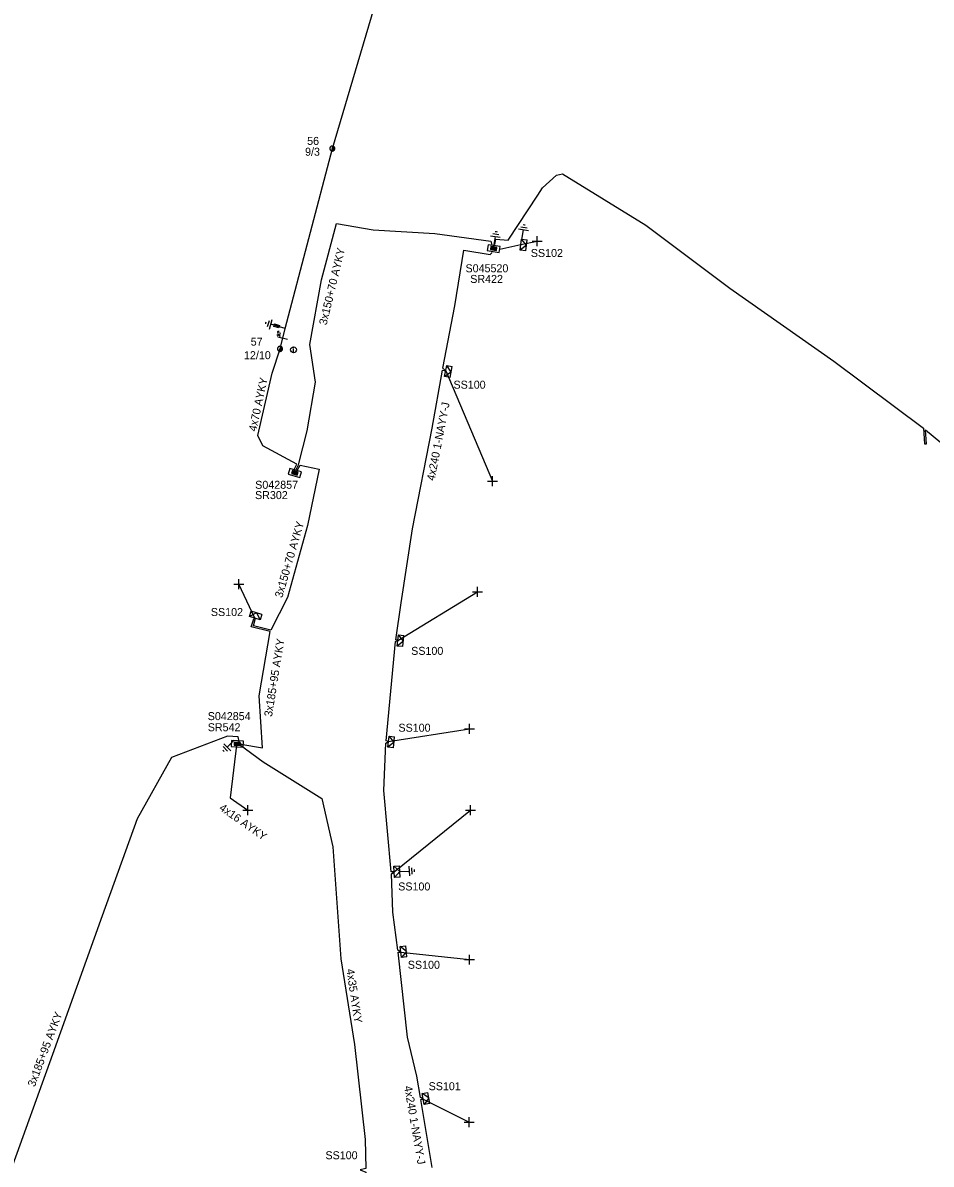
# Model space of a CAD drawing. Extents: x -748492 to -735633, y -1146251 to -1139940.
# Drawn here: x -736574.3 to -736460.8, y -1143691.4 to -1143548.7 of the extents above; entities that cross this region are included whole.
import ezdxf

# ---------------------------------------------------------------- set-up
doc = ezdxf.new("R2010")
doc.units = 0
for name, color, linetype in [('Vrstva 1', 7, 'Continuous'), ('Vrstva 10', 7, 'Continuous'), ('Vrstva 12', 7, 'Continuous'), ('Vrstva 13', 7, 'Continuous'), ('Vrstva 14', 7, 'Continuous'), ('Vrstva 15', 7, 'Continuous'), ('Vrstva 16', 7, 'Continuous'), ('Vrstva 18', 7, 'Continuous'), ('Vrstva 2', 7, 'Continuous'), ('Vrstva 28', 7, 'Continuous'), ('Vrstva 29', 7, 'Continuous'), ('Vrstva 30', 7, 'Continuous'), ('Vrstva 31', 7, 'Continuous'), ('Vrstva 33', 7, 'Continuous'), ('Vrstva 34', 7, 'Continuous'), ('Vrstva 36', 7, 'Continuous'), ('Vrstva 5', 7, 'Continuous'), ('Vrstva 52', 7, 'Continuous'), ('Vrstva 54', 7, 'Continuous'), ('Vrstva 59', 7, 'Continuous'), ('Vrstva 6', 7, 'Continuous'), ('Vrstva 8', 7, 'Continuous'), ('Vrstva 9', 7, 'Continuous')]:
    doc.layers.add(name, color=color, linetype=linetype)

# ---------------------------------------------------------------- blocks, each defined once
blk = doc.blocks.new('NN440')
at = {"layer": 'Vrstva 2'}
for points in [[(0.63, 0), (0.63, 0.06), (0.62, 0.13), (0.6, 0.19), (0.58, 0.25), (0.55, 0.31), (0.51, 0.37), (0.47, 0.42), (0.42, 0.46), (0.37, 0.51), (0.32, 0.54), (0.26, 0.57), (0.2, 0.59), (0.13, 0.61), (0.07, 0.62), (0, 0.63), (-0.06, 0.62), (-0.13, 0.61), (-0.19, 0.59), (-0.26, 0.57), (-0.31, 0.54), (-0.37, 0.51), (-0.42, 0.46), (-0.47, 0.42), (-0.51, 0.37), (-0.54, 0.31), (-0.57, 0.25), (-0.6, 0.19), (-0.62, 0.13), (-0.63, 0.06), (-0.63, 0), (-0.63, -0.07), (-0.62, -0.14), (-0.6, -0.2), (-0.57, -0.26), (-0.54, -0.32), (-0.51, -0.37), (-0.47, -0.43), (-0.42, -0.47), (-0.37, -0.51), (-0.31, -0.55), (-0.26, -0.58), (-0.19, -0.6), (-0.13, -0.62), (-0.06, -0.63), (0, -0.63), (0.07, -0.63), (0.13, -0.62), (0.2, -0.6), (0.26, -0.58), (0.32, -0.55), (0.37, -0.51), (0.42, -0.47), (0.47, -0.43), (0.51, -0.37), (0.55, -0.32), (0.58, -0.26), (0.6, -0.2), (0.62, -0.14), (0.63, -0.07), (0.63, 0)], [(-0.63, 0), (0.63, 0)], [(-0.6, -0.18), (0.57, -0.18)], [(-0.51, -0.32), (0.5, -0.32)], [(-0.37, -0.47), (0.35, -0.47)]]:
    blk.add_lwpolyline(points, dxfattribs=at)
blk = doc.blocks.new('NN840')
at = {"layer": 'Vrstva 15'}
for points in [[(0, 0.62), (0, -0.63)], [(-0.75, -0.71), (-0.75, -0.66)], [(-0.73, -0.76), (-0.75, -0.71)], [(-0.66, -0.8), (-0.73, -0.76)], [(-0.63, -0.8), (-0.66, -0.8)], [(-0.56, -0.76), (-0.63, -0.8)], [(-0.54, -0.71), (-0.56, -0.76)], [(-0.54, -0.38), (-0.54, -0.71)], [(-0.33, -0.38), (-0.33, -0.8)], [(-0.33, -0.64), (-0.13, -0.38)], [(-0.26, -0.56), (-0.09, -0.8)]]:
    blk.add_lwpolyline(points, dxfattribs=at)
blk = doc.blocks.new('NN770')
at = {"layer": 'Vrstva 10'}
for p, q in [((0, 0.19), (0, 0.26)), ((0, -0.28), (0, 0.11))]:
    blk.add_line(p, q, dxfattribs=at)
blk.add_circle((0, -0.01), 0.375, dxfattribs=at)
blk = doc.blocks.new('NN800')
at = {"layer": 'Vrstva 1'}
for points in [[(-0.44, 0.44), (0.44, -0.44)], [(-0.44, -0.44), (0.44, 0.44)]]:
    blk.add_lwpolyline(points, dxfattribs=at)
blk = doc.blocks.new('NN820')
at = {"layer": 'Vrstva 13'}
for points in [[(0, 0), (0, -1.05)], [(-0.16, -0.81), (0.16, -0.81)], [(-0.16, -1.47), (-0.16, -0.81)], [(0, -1.05), (-0.06, -0.93)], [(0, -1.05), (0.06, -0.93)], [(0.16, -0.81), (0.16, -1.47)], [(0.16, -1.47), (-0.16, -1.47)], [(0, -1.47), (0, -1.87)]]:
    blk.add_lwpolyline(points, dxfattribs=at)
blk = doc.blocks.new('NN620')
at = {"layer": 'Vrstva 8'}
for points in [[(0.75, 0), (-0.75, 0)], [(-0.75, 0), (-0.75, -0.75)], [(0.75, -0.75), (0.75, 0)], [(-0.75, -0.75), (0.75, -0.75)], [(0.37, -0.18), (-0.38, -0.18)], [(-0.38, -0.18), (-0.38, -0.56)], [(-0.38, -0.56), (0.37, -0.56)], [(0.32, -0.23), (-0.33, -0.23)], [(-0.33, -0.23), (-0.33, -0.51)], [(-0.33, -0.51), (0.32, -0.51)], [(0.27, -0.27), (-0.28, -0.27)], [(-0.28, -0.27), (-0.28, -0.46)], [(-0.28, -0.46), (0.27, -0.46)], [(0.23, -0.32), (-0.23, -0.32)], [(-0.23, -0.32), (-0.23, -0.42)], [(-0.23, -0.42), (0.23, -0.42)], [(-0.19, -0.37), (0.19, -0.37)], [(0.23, -0.42), (0.23, -0.32)], [(0.27, -0.46), (0.27, -0.27)], [(0.32, -0.51), (0.32, -0.23)], [(0.37, -0.56), (0.37, -0.18)]]:
    blk.add_lwpolyline(points, dxfattribs=at)
blk = doc.blocks.new('NN630')
at = {"layer": 'Vrstva 9'}
for points in [[(0, -0.7), (-0.7, 0)], [(-0.7, -0.7), (-0.7, 0), (0.7, 0), (0.7, -0.7)], [(-0.7, -0.7), (0.7, -0.7)], [(0, -0.7), (0.7, 0)]]:
    blk.add_lwpolyline(points, dxfattribs=at)
blk = doc.blocks.new('NN810')
at = {"layer": 'Vrstva 14'}
for points in [[(0, -0.64), (0, -1.89)], [(0.63, -1.89), (-0.62, -1.89)], [(0.39, -2.2), (-0.4, -2.2)], [(0, -2.52), (-0.12, -2.52)], [(0.14, -2.52), (0, -2.52)]]:
    blk.add_lwpolyline(points, dxfattribs=at)

msp = doc.modelspace()

# ---------------------------------------------------------------- linework, layer by layer
at = {"layer": 'Vrstva 1'}
msp.add_lwpolyline([(-736542.15, -1143589.49), (-736541.49, -1143586.96), (-736535.61, -1143564.45), (-736528.19, -1143539.37), (-736522.07, -1143513.24)], dxfattribs=at)
at = {"layer": 'Vrstva 5'}
for points in [[(-736515.32, -1143576.46), (-736515.17, -1143575.77), (-736513.66, -1143575.89), (-736509.94, -1143570.26), (-736509.33, -1143569.38), (-736507.61, -1143567.78), (-736506.87, -1143567.6), (-736496.45, -1143574.03), (-736485.93, -1143581.91), (-736472.94, -1143591.01), (-736461.73, -1143599.42), (-736461.61, -1143601.38), (-736461.36, -1143601.36), (-736461.47, -1143599.62), (-736453.1, -1143606.51), (-736442.54, -1143614.26), (-736434.94, -1143619.81), (-736423.45, -1143627.86), (-736416.15, -1143633.12), (-736416.73, -1143634), (-736417.1, -1143633.9)], [(-736540.19, -1143604.64), (-736539.85, -1143603.98), (-736538.75, -1143599.72), (-736537.71, -1143593.65), (-736538.41, -1143588.96), (-736536.96, -1143580.85), (-736535.08, -1143573.83), (-736530.5, -1143574.62), (-736522.8, -1143575.07), (-736515.82, -1143576.03), (-736515.7, -1143576.52)], [(-736514.69, -1143577.04), (-736512.06, -1143576.46)], [(-736523.15, -1143691.81), (-736524.57, -1143683.32), (-736524.25, -1143683.26), (-736524.61, -1143683.08), (-736525.07, -1143680.42), (-736526.2, -1143675.54), (-736527.37, -1143664.91), (-736527.06, -1143664.89), (-736527.41, -1143664.64), (-736528.05, -1143659.91), (-736528.23, -1143655.11), (-736527.89, -1143654.87), (-736528.24, -1143654.88), (-736529.17, -1143644.71), (-736528.91, -1143638.78), (-736528.6, -1143638.59), (-736528.9, -1143638.5), (-736527.7, -1143626.09), (-736527.43, -1143625.94), (-736527.68, -1143625.85), (-736527.01, -1143621.25), (-736525.59, -1143611.98), (-736523.13, -1143599.41), (-736521.86, -1143592.16), (-736521.45, -1143592.25), (-736521.81, -1143591.9), (-736520.29, -1143584.12), (-736519.18, -1143577.15), (-736515.87, -1143577.69), (-736515.62, -1143577.43)], [(-736540.39, -1143604.58), (-736540.03, -1143603.89), (-736544.29, -1143601.63), (-736544.93, -1143600.33), (-736543.15, -1143592.53), (-736542.15, -1143589.49)], [(-736539.99, -1143604.7), (-736539.65, -1143604.02), (-736537.24, -1143604.52), (-736538.7, -1143611.59), (-736541.23, -1143620.59), (-736543.3, -1143624.64), (-736545.48, -1143624.11), (-736545.25, -1143623.32), (-736545.3, -1143623.15)], [(-736547.11, -1143638.69), (-736547.06, -1143638.89), (-736544.35, -1143639.36), (-736544.76, -1143632.86), (-736543.37, -1143624.83), (-736545.74, -1143624.25), (-736545.44, -1143623.25), (-736545.3, -1143623.15)], [(-736547.25, -1143638.56), (-736547.4, -1143637.97), (-736548.7, -1143637.89), (-736555.69, -1143640.57), (-736559.98, -1143648.22), (-736564.36, -1143660.36), (-736570.59, -1143677.69), (-736575.95, -1143692.63), (-736580.47, -1143701.63), (-736583.04, -1143702.99), (-736590.32, -1143701.54), (-736594.79, -1143700.58), (-736606.16, -1143696.36), (-736617.69, -1143691.44), (-736617.29, -1143689.85)], [(-736547.32, -1143638.69), (-736547.27, -1143638.89), (-736544.27, -1143641.1), (-736536.92, -1143645.7), (-736535.56, -1143651.72), (-736534.56, -1143665.73), (-736532.86, -1143676.43), (-736531.53, -1143688.34), (-736531.41, -1143691.93), (-736532.12, -1143692.13), (-736531.43, -1143692.42), (-736530.87, -1143708.45), (-736532.82, -1143708.54)]]:
    msp.add_lwpolyline(points, dxfattribs=at)
at = {"layer": 'Vrstva 52'}
msp.add_lwpolyline([(-736547.55, -1143638.68), (-736548.39, -1143645.61), (-736546.17, -1143647.17)], dxfattribs=at)
at = {"layer": 'Vrstva 59'}
for points in [[(-736512.06, -1143576.46), (-736510.03, -1143576.02)], [(-736521.45, -1143592.25), (-736515.59, -1143606.02)], [(-736545.3, -1143623.15), (-736547.3, -1143618.9)], [(-736527.43, -1143625.94), (-736517.46, -1143619.86)], [(-736528.6, -1143638.59), (-736518.46, -1143637)], [(-736527.89, -1143654.87), (-736518.35, -1143647.16)], [(-736527.06, -1143664.89), (-736518.47, -1143665.83)], [(-736524.25, -1143683.26), (-736518.53, -1143686.16)]]:
    msp.add_lwpolyline(points, dxfattribs=at)

# ---------------------------------------------------------------- block references
at = {"layer": 'Vrstva 13', "xscale": 0.5}
for p, yscale, rotation in [((-736535.61, -1143564.45), 0.5, 75.52877971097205), ((-736542.15, -1143589.49), 0.49999999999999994, 73.19172953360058)]:
    msp.add_blockref('NN440', p, dxfattribs=dict(at, yscale=yscale, rotation=rotation))
at = {"layer": 'Vrstva 15'}
for p, rotation in [((-736515.51, -1143577.32), 171.58488063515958), ((-736512.06, -1143576.46), 169.89343216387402), ((-736541.49, -1143586.96), -106.87135837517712), ((-736547.4, -1143637.97), -45.815225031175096), ((-736527.89, -1143654.87), 93.25958050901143)]:
    msp.add_blockref('NN810', p, dxfattribs=dict(at, rotation=rotation))
at = {"layer": 'Vrstva 16', "rotation": -106.87135837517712}
msp.add_blockref('NN820', (-736541.49, -1143586.96), dxfattribs=at)
at = {"layer": 'Vrstva 18', "rotation": -104.637639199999}
msp.add_blockref('NN840', (-736541.81, -1143588.18), dxfattribs=at)
at = {"layer": 'Vrstva 28'}
for p, rotation in [((-736515.51, -1143577.32), 171.58488063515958), ((-736540.19, -1143604.64), -15.97215494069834), ((-736547.51, -1143639.24), 177.8443742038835)]:
    msp.add_blockref('NN620', p, dxfattribs=dict(at, rotation=rotation))
at = {"layer": 'Vrstva 31'}
for p, rotation in [((-736512.06, -1143576.46), 82.88903651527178), ((-736521.45, -1143592.25), 78.38320282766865), ((-736545.3, -1143623.15), 163.58276707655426), ((-736527.43, -1143625.94), 84.11062216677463), ((-736528.6, -1143638.59), 83.83935554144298), ((-736527.89, -1143654.87), 93.25958057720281), ((-736527.06, -1143664.89), 96.40244716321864), ((-736524.25, -1143683.26), 100.61109438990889)]:
    msp.add_blockref('NN630', p, dxfattribs=dict(at, rotation=rotation))
at = {"layer": 'Vrstva 34'}
for p, rotation in [((-736510.03, -1143576.03), 45), ((-736515.59, -1143606.02), 45), ((-736547.3, -1143618.9), 45), ((-736517.46, -1143619.87), 45), ((-736518.46, -1143637), 45), ((-736546.17, -1143647.17), 45), ((-736518.35, -1143647.16), 45), ((-736518.47, -1143665.84), 45), ((-736518.53, -1143686.16), 45.00000009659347)]:
    msp.add_blockref('NN800', p, dxfattribs=dict(at, rotation=rotation))
at = {"layer": 'Vrstva 36'}
msp.add_blockref('NN770', (-736540.46, -1143589.6), dxfattribs=at)

# ---------------------------------------------------------------- texts
at = {"layer": 'Vrstva 12'}
for s, p in [('9/3', (-736539.02, -1143565.35)), ('12/10', (-736546.65, -1143590.78))]:
    msp.add_text(s, height=1, dxfattribs=at).set_placement(p)
at = {"layer": 'Vrstva 14'}
for s, p in [('56', (-736538.76, -1143564)), ('57', (-736545.81, -1143589.09))]:
    msp.add_text(s, height=1, dxfattribs=at).set_placement(p)
at = {"layer": 'Vrstva 29'}
for s, p in [('S045520', (-736518.97, -1143579.92)), ('S042857', (-736545.25, -1143606.98)), ('S042854', (-736551.18, -1143635.9))]:
    msp.add_text(s, height=1, dxfattribs=at).set_placement(p)
at = {"layer": 'Vrstva 30'}
for s, p in [('SR422', (-736518.38, -1143581.25)), ('SR302', (-736545.27, -1143608.27)), ('SR542', (-736551.18, -1143637.29))]:
    msp.add_text(s, height=1, dxfattribs=at).set_placement(p)
at = {"layer": 'Vrstva 33'}
for s, p in [('SS102', (-736510.81, -1143578.01)), ('SS100', (-736520.47, -1143594.47)), ('SS102', (-736550.79, -1143622.89)), ('SS100', (-736525.76, -1143627.74)), ('SS100', (-736527.35, -1143637.35)), ('SS100', (-736527.38, -1143657.19)), ('SS100', (-736526.18, -1143666.98)), ('SS101', (-736523.58, -1143682.16)), ('SS100', (-736536.47, -1143690.79))]:
    msp.add_text(s, height=1, dxfattribs=at).set_placement(p)
at = {"layer": 'Vrstva 54'}
msp.add_text('4x16 AYKY', height=1, rotation=324.928, dxfattribs=at).set_placement((-736549.84, -1143647.07))
at = {"layer": 'Vrstva 6'}
for s, rotation, p in [('3x150+70 AYKY', 76.421, (-736536.33, -1143586.58)), ('4x70 AYKY', 77.71, (-736545.13, -1143599.88)), ('4x240 1-NAYY-J', 78.927, (-736522.85, -1143606.04)), ('3x150+70 AYKY', 73.811, (-736541.88, -1143620.69)), ('3x185+95 AYKY', 80.754, (-736543.16, -1143635.53)), ('4x35 AYKY', 278.586, (-736533.87, -1143667.06)), ('3x185+95 AYKY', 69.34, (-736572.8, -1143681.82)), ('4x240 1-NAYY-J', 279.78, (-736526.64, -1143681.69))]:
    msp.add_text(s, height=1, rotation=rotation, dxfattribs=at).set_placement(p)

doc.saveas('drawing.dxf')
